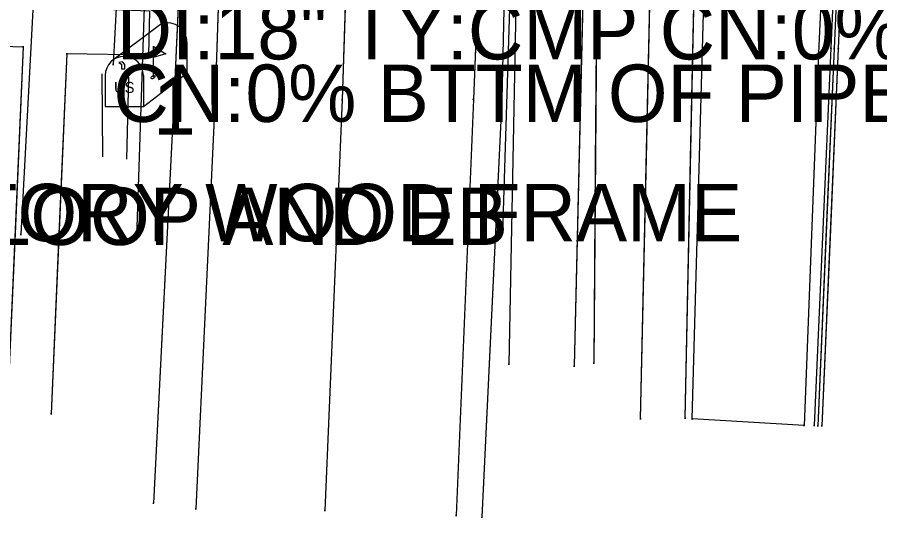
# Model space of a CAD drawing. Extents: x -99999 to 591807, y -99999 to 347168.
# Drawn here: x 591214 to 591289.1, y 320423.8 to 320467.4 of the extents above; entities that cross this region are included whole.
import ezdxf

# ---------------------------------------------------------------- set-up
doc = ezdxf.new("R2010")
doc.units = 0
for name, color, linetype in [('S_BREAKLINE', 7, 'Continuous'), ('S_CURB', 7, 'Continuous'), ('S_DITCHLINE', 7, 'Continuous'), ('S_DRG_PT_SYM', 7, 'Continuous'), ('S_EDGE_PAVEMENT', 7, 'Continuous'), ('S_GAS_UTILITIES', 7, 'Continuous'), ('S_GRD_PT_SYM', 7, 'Continuous'), ('S_MAILBOX', 7, 'Continuous'), ('S_MAILBOX_ANNOT', 7, 'Continuous'), ('S_MISC_STRUCTURES_ANNOT', 7, 'Continuous'), ('S_MSC_PT_SYM', 7, 'Continuous'), ('S_PAVEMENT_CROWN', 7, 'Continuous'), ('S_RDW_PT_SYM', 7, 'Continuous'), ('S_SHOULDER', 7, 'Continuous'), ('S_SIDE_DRAIN', 7, 'Continuous'), ('S_SIDE_DRAIN_ANNOT', 7, 'Continuous'), ('S_SIDEWALK', 7, 'Continuous'), ('S_SURVEY_TEXT_ANNOT', 7, 'Continuous'), ('S_UTL_PT_SYM', 7, 'Continuous'), ('S_WATER_UTILITIES', 7, 'Continuous')]:
    doc.layers.add(name, color=color, linetype=linetype)

msp = doc.modelspace()

# ---------------------------------------------------------------- linework, layer by layer
at = {"layer": 'S_BREAKLINE'}
for points in [[(591274.782, 320513.065), (591281.897, 320511.813), (591285.735, 320505.983), (591283.815, 320464.224), (591282.55, 320431.813), (591272.787, 320432.375), (591274.038, 320477.077), (591274.782, 320513.065)], [(591268.263, 320477.868), (591268.875, 320512.065), (591261.464, 320507.738), (591257.934, 320493.542), (591256.832, 320437.153)]]:
    msp.add_lwpolyline(points, dxfattribs=at)
at = {"layer": 'S_CURB'}
for points in [[(591285.989, 320509.301), (591286.579, 320507.16), (591286.616, 320504.303), (591284.881, 320464.653), (591283.444, 320431.794)], [(591285.989, 320509.301), (591286.579, 320507.16), (591286.616, 320504.303), (591285.749, 320484.478), (591284.881, 320464.653), (591284.163, 320448.223), (591283.444, 320431.794)], [(591286.278, 320509.38), (591286.878, 320507.203), (591286.916, 320504.299), (591285.181, 320464.64), (591283.744, 320431.781)], [(591286.278, 320509.38), (591286.878, 320507.203), (591286.916, 320504.299), (591286.049, 320484.469), (591285.181, 320464.64), (591284.463, 320448.21), (591283.744, 320431.781)], [(591286.615, 320509.473), (591287.228, 320507.253), (591287.266, 320504.293), (591285.53, 320464.624), (591284.094, 320431.766)], [(591286.615, 320509.473), (591287.228, 320507.253), (591287.266, 320504.293), (591286.398, 320484.458), (591285.53, 320464.624), (591284.812, 320448.195), (591284.094, 320431.766)]]:
    msp.add_lwpolyline(points, dxfattribs=at)
at = {"layer": 'S_DITCHLINE'}
for points in [[(591264.171, 320506.495), (591262.52, 320436.964)], [(591264.171, 320506.495), (591263.758, 320489.112), (591263.345, 320471.729), (591262.932, 320454.346), (591262.52, 320436.964)], [(591264.77, 320506.449), (591264.224, 320437.239)], [(591264.77, 320506.449), (591264.633, 320489.147), (591264.497, 320471.844), (591264.36, 320454.541), (591264.224, 320437.239)], [(591221.459, 320455.192), (591221.379, 320462.421)], [(591223.524, 320454.985), (591223.7, 320462.146)]]:
    msp.add_lwpolyline(points, dxfattribs=at)
at = {"layer": 'S_DRG_PT_SYM'}
msp.add_lwpolyline([(591222.362, 320463.238), (591222.362, 320463.288), (591222.362, 320463.238), (591222.312, 320463.238), (591222.362, 320463.238), (591222.362, 320463.188), (591222.362, 320463.238), (591222.412, 320463.238)], dxfattribs=at)
at = {"layer": 'S_EDGE_PAVEMENT'}
for points in [[(591157.816, 321374.558), (591171.996, 321326.2), (591184.501, 321283.667), (591196.965, 321241.411), (591212.283, 321187.826), (591223.284, 321148.219), (591233.116, 321106.873), (591242.974, 321050.292), (591247.278, 321006.148), (591248.487, 320958.254), (591248.173, 320914.304), (591247.117, 320868.716), (591245.559, 320824.189), (591244.165, 320785.581), (591242.251, 320742.557), (591240.726, 320705.613), (591238.924, 320663.696), (591237.267, 320623.329), (591235.848, 320588.307), (591234.304, 320543.116), (591232.694, 320503.413), (591231.224, 320460.428), (591229.562, 320424.545)], [(591276.464, 321095.169), (591275.056, 321053.597), (591273.291, 321005.346), (591272, 320957.38), (591270.852, 320912.706), (591269.626, 320868.123), (591267.967, 320823.163), (591266.366, 320784.972), (591264.567, 320741.355), (591263.052, 320704.522), (591261.343, 320660.719), (591259.642, 320623.868), (591258.44, 320586.063), (591256.824, 320543.024), (591255.332, 320500.726), (591253.745, 320460.208), (591252.238, 320423.96)], [(591236.557, 320605.818), (591235.848, 320588.307), (591235.076, 320565.712), (591234.304, 320543.116), (591233.499, 320523.265), (591232.694, 320503.413), (591231.959, 320481.921), (591231.224, 320460.428), (591230.393, 320442.487), (591229.562, 320424.545)], [(591259.041, 320604.965), (591258.44, 320586.063), (591257.632, 320564.544), (591256.824, 320543.024), (591256.078, 320521.875), (591255.332, 320500.726), (591254.539, 320480.467), (591253.745, 320460.208), (591252.991, 320442.084), (591252.238, 320423.96)]]:
    msp.add_lwpolyline(points, dxfattribs=at)
at = {"layer": 'S_GAS_UTILITIES'}
msp.add_line((591229.99, 320612.067), (591224.377, 320448.24), dxfattribs=at)
at = {"layer": 'S_GRD_PT_SYM'}
for points in [[(591283.815, 320464.224), (591283.815, 320464.274), (591283.815, 320464.224), (591283.765, 320464.224), (591283.815, 320464.224), (591283.815, 320464.175), (591283.815, 320464.224), (591283.865, 320464.224)], [(591283.815, 320464.224), (591283.865, 320464.223), (591283.815, 320464.224), (591283.817, 320464.274), (591283.815, 320464.224), (591283.765, 320464.226), (591283.815, 320464.224), (591283.813, 320464.175)], [(591256.832, 320437.153), (591256.882, 320437.152), (591256.832, 320437.153), (591256.833, 320437.203), (591256.832, 320437.153), (591256.782, 320437.154), (591256.832, 320437.153), (591256.831, 320437.103)], [(591262.52, 320436.964), (591262.57, 320436.962), (591262.52, 320436.964), (591262.521, 320437.014), (591262.52, 320436.964), (591262.47, 320436.965), (591262.52, 320436.964), (591262.518, 320436.914)], [(591264.224, 320437.239), (591264.274, 320437.238), (591264.224, 320437.239), (591264.224, 320437.289), (591264.224, 320437.239), (591264.174, 320437.239), (591264.224, 320437.239), (591264.223, 320437.189)], [(591272.787, 320432.375), (591272.787, 320432.425), (591272.787, 320432.375), (591272.737, 320432.375), (591272.787, 320432.375), (591272.787, 320432.325), (591272.787, 320432.375), (591272.837, 320432.375)], [(591272.787, 320432.375), (591272.737, 320432.377), (591272.787, 320432.375), (591272.786, 320432.325), (591272.787, 320432.375), (591272.837, 320432.374), (591272.787, 320432.375), (591272.789, 320432.425)], [(591282.55, 320431.813), (591282.55, 320431.863), (591282.55, 320431.813), (591282.5, 320431.813), (591282.55, 320431.813), (591282.55, 320431.763), (591282.55, 320431.813), (591282.6, 320431.813)], [(591282.55, 320431.813), (591282.547, 320431.763), (591282.55, 320431.813), (591282.6, 320431.81), (591282.55, 320431.813), (591282.553, 320431.863), (591282.55, 320431.813), (591282.5, 320431.816)]]:
    msp.add_lwpolyline(points, close=True, dxfattribs=at)
at = {"layer": 'S_MAILBOX'}
for p, q in [((591222.21, 320463.563), (591226.345, 320466.671)), ((591225.826, 320464.851), (591225.826, 320462.136)), ((591228.776, 320465.197), (591228.776, 320462.482)), ((591221.656, 320462.288), (591221.656, 320459.573)), ((591224.981, 320459.573), (591228.776, 320462.482)), ((591224.981, 320462.288), (591224.981, 320459.573)), ((591221.656, 320459.573), (591224.981, 320459.573))]:
    msp.add_line(p, q, dxfattribs=at)
for points in [[(591225.826, 320464.851), (591226.934, 320464.186), (591225.826, 320463.84)], [(591222.841, 320463.403), (591223.062, 320463.265), (591223.062, 320462.877), (591223.367, 320462.877), (591223.367, 320463.237), (591223.173, 320463.487), (591222.841, 320463.431)]]:
    msp.add_lwpolyline(points, dxfattribs=at)
for centre, end in [((591227.114, 320465.197), 117.57184), ((591223.318, 320462.288), 180)]:
    msp.add_arc(centre, 1.662, 0, end, dxfattribs=at)
msp.add_ellipse((591225.826, 320462.136), major_axis=(0.145, 0.132), ratio=0.564646, dxfattribs=at)
at = {"layer": 'S_MSC_PT_SYM'}
for points in [[(591214.509, 320464.774), (591214.559, 320464.771), (591214.509, 320464.774), (591214.511, 320464.824), (591214.509, 320464.774), (591214.459, 320464.776), (591214.509, 320464.774), (591214.507, 320464.724)], [(591218.297, 320464.183), (591218.347, 320464.181), (591218.297, 320464.183), (591218.3, 320464.233), (591218.297, 320464.183), (591218.248, 320464.186), (591218.297, 320464.183), (591218.295, 320464.134)], [(591225.412, 320464.068), (591225.411, 320464.018), (591225.412, 320464.068), (591225.462, 320464.067), (591225.412, 320464.068), (591225.413, 320464.117), (591225.412, 320464.068), (591225.362, 320464.068)], [(591216.954, 320432.825), (591217.003, 320432.823), (591216.954, 320432.825), (591216.956, 320432.875), (591216.954, 320432.825), (591216.904, 320432.827), (591216.954, 320432.825), (591216.951, 320432.775)], [(591268.303, 320432.387), (591268.253, 320432.388), (591268.303, 320432.387), (591268.302, 320432.337), (591268.303, 320432.387), (591268.353, 320432.386), (591268.303, 320432.387), (591268.304, 320432.437)], [(591272.189, 320432.435), (591272.139, 320432.436), (591272.189, 320432.435), (591272.188, 320432.385), (591272.189, 320432.435), (591272.239, 320432.434), (591272.189, 320432.435), (591272.19, 320432.485)]]:
    msp.add_lwpolyline(points, close=True, dxfattribs=at)
at = {"layer": 'S_PAVEMENT_CROWN'}
for points in [[(591169.393, 321376.166), (591182.702, 321330.303), (591196.053, 321285.507), (591208.234, 321244.204), (591224.138, 321189.501), (591234.43, 321151.835), (591245.74, 321106.049), (591255.457, 321050.575), (591259.103, 321006.376), (591260.258, 320958.142), (591259.827, 320913.406), (591258.406, 320868.937), (591257.042, 320823.073), (591255.423, 320785.261), (591253.776, 320741.805), (591252.116, 320704.89), (591250.293, 320661.391), (591248.847, 320623.224), (591247.409, 320587.797), (591245.838, 320543.645), (591243.645, 320502.375), (591242.309, 320460.161), (591240.802, 320424.401)], [(591248.128, 320605.51), (591247.409, 320587.797), (591246.623, 320565.721), (591245.838, 320543.645), (591244.741, 320523.01), (591243.645, 320502.375), (591242.977, 320481.268), (591242.309, 320460.161), (591241.556, 320442.281), (591240.802, 320424.401)]]:
    msp.add_lwpolyline(points, dxfattribs=at)
at = {"layer": 'S_RDW_PT_SYM'}
for points in [[(591284.881, 320464.653), (591284.931, 320464.65), (591284.881, 320464.653), (591284.883, 320464.703), (591284.881, 320464.653), (591284.831, 320464.655), (591284.881, 320464.653), (591284.879, 320464.603)], [(591285.181, 320464.64), (591285.231, 320464.637), (591285.181, 320464.64), (591285.183, 320464.69), (591285.181, 320464.64), (591285.131, 320464.642), (591285.181, 320464.64), (591285.179, 320464.59)], [(591285.53, 320464.624), (591285.58, 320464.621), (591285.53, 320464.624), (591285.532, 320464.674), (591285.53, 320464.624), (591285.48, 320464.626), (591285.53, 320464.624), (591285.528, 320464.574)], [(591227.673, 320460.661), (591227.723, 320460.659), (591227.673, 320460.661), (591227.676, 320460.711), (591227.673, 320460.661), (591227.623, 320460.664), (591227.673, 320460.661), (591227.671, 320460.611)], [(591231.224, 320460.428), (591231.274, 320460.426), (591231.224, 320460.428), (591231.227, 320460.478), (591231.224, 320460.428), (591231.174, 320460.431), (591231.224, 320460.428), (591231.222, 320460.378)], [(591242.309, 320460.161), (591242.359, 320460.159), (591242.309, 320460.161), (591242.311, 320460.211), (591242.309, 320460.161), (591242.259, 320460.163), (591242.309, 320460.161), (591242.307, 320460.111)], [(591253.745, 320460.208), (591253.795, 320460.206), (591253.745, 320460.208), (591253.747, 320460.258), (591253.745, 320460.208), (591253.695, 320460.21), (591253.745, 320460.208), (591253.743, 320460.158)], [(591256.224, 320460.204), (591256.274, 320460.202), (591256.224, 320460.204), (591256.227, 320460.254), (591256.224, 320460.204), (591256.174, 320460.207), (591256.224, 320460.204), (591256.222, 320460.154)], [(591283.444, 320431.794), (591283.494, 320431.792), (591283.444, 320431.794), (591283.446, 320431.844), (591283.444, 320431.794), (591283.394, 320431.796), (591283.444, 320431.794), (591283.442, 320431.744)], [(591283.744, 320431.781), (591283.794, 320431.779), (591283.744, 320431.781), (591283.746, 320431.831), (591283.744, 320431.781), (591283.694, 320431.783), (591283.744, 320431.781), (591283.742, 320431.731)], [(591284.094, 320431.766), (591284.144, 320431.764), (591284.094, 320431.766), (591284.096, 320431.816), (591284.094, 320431.766), (591284.044, 320431.768), (591284.094, 320431.766), (591284.092, 320431.716)], [(591225.848, 320425.042), (591225.898, 320425.039), (591225.848, 320425.042), (591225.851, 320425.092), (591225.848, 320425.042), (591225.798, 320425.044), (591225.848, 320425.042), (591225.846, 320424.992)], [(591229.562, 320424.545), (591229.612, 320424.542), (591229.562, 320424.545), (591229.565, 320424.595), (591229.562, 320424.545), (591229.512, 320424.547), (591229.562, 320424.545), (591229.56, 320424.495)], [(591240.802, 320424.401), (591240.852, 320424.399), (591240.802, 320424.401), (591240.804, 320424.451), (591240.802, 320424.401), (591240.752, 320424.403), (591240.802, 320424.401), (591240.8, 320424.351)], [(591252.238, 320423.96), (591252.288, 320423.958), (591252.238, 320423.96), (591252.24, 320424.01), (591252.238, 320423.96), (591252.188, 320423.962), (591252.238, 320423.96), (591252.236, 320423.91)], [(591254.486, 320423.814), (591254.536, 320423.811), (591254.486, 320423.814), (591254.488, 320423.864), (591254.486, 320423.814), (591254.436, 320423.816), (591254.486, 320423.814), (591254.484, 320423.764)]]:
    msp.add_lwpolyline(points, close=True, dxfattribs=at)
at = {"layer": 'S_SHOULDER'}
for points in [[(591245.875, 320932.116), (591246.336, 320914.379), (591244.03, 320869.095), (591242.236, 320824.086), (591240.926, 320786.072), (591238.956, 320744.968), (591237.561, 320705.47), (591236.035, 320663.813), (591234.455, 320624.274), (591233.024, 320588.472), (591231.51, 320542.985), (591229.6, 320503.548), (591227.673, 320460.661), (591225.848, 320425.042)], [(591233.739, 320606.373), (591233.024, 320588.472), (591232.267, 320565.729), (591231.51, 320542.985), (591230.555, 320523.267), (591229.6, 320503.548), (591228.637, 320482.105), (591227.673, 320460.661), (591226.761, 320442.852), (591225.848, 320425.042)], [(591256.52, 320504.865), (591257.195, 320504.626), (591256.224, 320460.204), (591254.486, 320423.814)], [(591256.52, 320504.865), (591257.195, 320504.626), (591256.71, 320482.415), (591256.224, 320460.204), (591255.355, 320442.009), (591254.486, 320423.814)]]:
    msp.add_lwpolyline(points, dxfattribs=at)
at = {"layer": 'S_SIDE_DRAIN'}
msp.add_line((591222.642, 320468.688), (591222.362, 320463.238), dxfattribs=at)
at = {"layer": 'S_SIDEWALK'}
for points in [[(591225.013, 320617.584), (591223.33, 320575.279), (591221.529, 320534.239), (591221.586, 320536.045), (591219.997, 320501.136), (591218.495, 320468.181), (591225.523, 320467.907), (591225.412, 320464.068), (591218.297, 320464.183), (591216.954, 320432.825)], [(591225.013, 320617.584), (591224.171, 320596.432), (591223.33, 320575.279), (591222.429, 320554.759), (591221.529, 320534.239), (591221.586, 320536.045), (591220.791, 320518.59), (591219.997, 320501.136), (591219.246, 320484.658), (591218.495, 320468.181), (591225.523, 320467.907), (591225.412, 320464.068), (591218.297, 320464.183), (591217.625, 320448.504), (591216.954, 320432.825)], [(591268.303, 320432.387), (591269.318, 320477.799), (591270.077, 320513.547)], [(591268.303, 320432.387), (591268.811, 320455.093), (591269.318, 320477.799), (591269.698, 320495.673), (591270.077, 320513.547)], [(591272.189, 320432.435), (591273.149, 320477.704), (591274.06, 320513.444)], [(591272.189, 320432.435), (591272.669, 320455.069), (591273.149, 320477.704), (591273.605, 320495.574), (591274.06, 320513.444)], [(591201.028, 320465.211), (591214.509, 320464.774), (591213.142, 320433.62)], [(591201.028, 320465.211), (591214.509, 320464.774), (591213.826, 320449.197), (591213.142, 320433.62)]]:
    msp.add_lwpolyline(points, dxfattribs=at)
at = {"layer": 'S_UTL_PT_SYM'}
for points in [[(591214.304, 320448.446), (591214.304, 320448.496), (591214.304, 320448.446), (591214.254, 320448.446), (591214.304, 320448.446), (591214.304, 320448.396), (591214.304, 320448.446), (591214.354, 320448.446)], [(591224.377, 320448.24), (591224.377, 320448.29), (591224.377, 320448.24), (591224.327, 320448.24), (591224.377, 320448.24), (591224.377, 320448.19), (591224.377, 320448.24), (591224.427, 320448.24)], [(591256.284, 320448.599), (591256.284, 320448.649), (591256.284, 320448.599), (591256.234, 320448.599), (591256.284, 320448.599), (591256.284, 320448.549), (591256.284, 320448.599), (591256.334, 320448.599)]]:
    msp.add_lwpolyline(points, dxfattribs=at)
at = {"layer": 'S_WATER_UTILITIES'}
for p, q in [((591262.693, 320654.847), (591256.284, 320448.599)), ((591223.46, 320618.063), (591214.304, 320448.446))]:
    msp.add_line(p, q, dxfattribs=at)

# ---------------------------------------------------------------- texts
at = {"layer": 'S_MAILBOX'}
msp.add_text('US', height=0.96, rotation=360, dxfattribs=at).set_placement((591222.42, 320460.767))
at = {"layer": 'S_MAILBOX_ANNOT'}
msp.add_text('1', height=5, dxfattribs=at).set_placement((591225.826, 320457.136))
at = {"layer": 'S_MISC_STRUCTURES_ANNOT'}
msp.add_text('METERLOOP AND EB', height=5, dxfattribs=at).set_placement((591188.018, 320447.521))
at = {"layer": 'S_SIDE_DRAIN_ANNOT'}
for s, p in [('DI:18" TY:CMP CN:0% BTTM OF PIP', (591222.642, 320463.688)), ('CN:0% BTTM OF PIPE', (591222.362, 320458.238))]:
    msp.add_text(s, height=5, dxfattribs=at).set_placement(p)
at = {"layer": 'S_SURVEY_TEXT_ANNOT'}
msp.add_text('ONE STORY WOOD FRAME', height=5, dxfattribs=at).set_placement((591189.123, 320447.847))

doc.saveas('drawing.dxf')
